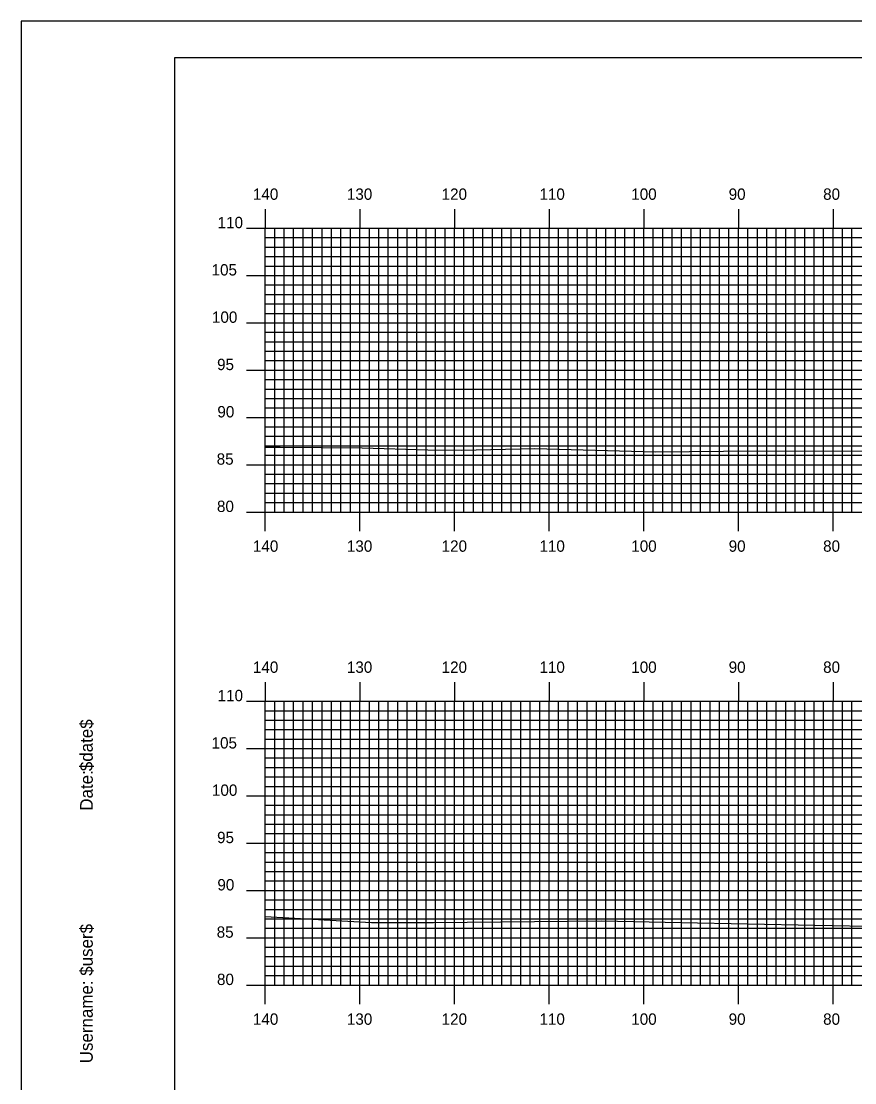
# Model space of a CAD drawing. Extents: x 1762578 to 1762921, y 442591 to 442811.
# Drawn here: x 1762578 to 1762666.1, y 442698.3 to 442810.5 of the extents above; entities that cross this region are included whole.
import ezdxf

# ---------------------------------------------------------------- set-up
doc = ezdxf.new("R2010")
doc.units = 0
for name, color, linetype in [('BORDER', 7, 'Continuous'), ('H_V ANNOTATION', 7, 'Continuous'), ('MAJOR', 7, 'Continuous'), ('MINOR', 7, 'Continuous'), ('PLOT BOUNDARY', 7, 'Continuous'), ('S_Roadway_Centerline', 7, 'Continuous')]:
    doc.layers.add(name, color=color, linetype=linetype)

msp = doc.modelspace()

# ---------------------------------------------------------------- linework, layer by layer
at = {"layer": 'BORDER'}
msp.add_lwpolyline([(1762594.18, 442596.67), (1762914.18, 442596.67), (1762914.18, 442806.67), (1762594.18, 442806.67)], close=True, dxfattribs=at)
at = {"layer": 'MAJOR'}
for p, q in [((1762603.78, 442790.67), (1762603.78, 442788.67)), ((1762613.78, 442790.67), (1762613.78, 442788.67)), ((1762623.78, 442790.67), (1762623.78, 442788.67)), ((1762633.78, 442790.67), (1762633.78, 442788.67)), ((1762643.78, 442790.67), (1762643.78, 442788.67)), ((1762653.78, 442790.67), (1762653.78, 442788.67)), ((1762663.78, 442790.67), (1762663.78, 442788.67)), ((1762601.78, 442788.67), (1762603.78, 442788.67)), ((1762603.78, 442788.67), (1762883.78, 442788.67)), ((1762603.78, 442758.67), (1762603.78, 442788.67)), ((1762603.78, 442758.67), (1762603.78, 442788.67)), ((1762603.78, 442788.67), (1762883.78, 442788.67)), ((1762613.78, 442758.67), (1762613.78, 442788.67)), ((1762623.78, 442758.67), (1762623.78, 442788.67)), ((1762633.78, 442758.67), (1762633.78, 442788.67)), ((1762643.78, 442758.67), (1762643.78, 442788.67)), ((1762653.78, 442758.67), (1762653.78, 442788.67)), ((1762663.78, 442758.67), (1762663.78, 442788.67)), ((1762601.78, 442783.67), (1762603.78, 442783.67)), ((1762603.78, 442783.67), (1762883.78, 442783.67)), ((1762601.78, 442778.67), (1762603.78, 442778.67)), ((1762603.78, 442778.67), (1762883.78, 442778.67)), ((1762601.78, 442773.67), (1762603.78, 442773.67)), ((1762603.78, 442773.67), (1762883.78, 442773.67)), ((1762601.78, 442768.67), (1762603.78, 442768.67)), ((1762603.78, 442768.67), (1762883.78, 442768.67)), ((1762601.78, 442763.67), (1762603.78, 442763.67)), ((1762603.78, 442763.67), (1762883.78, 442763.67)), ((1762601.78, 442758.67), (1762603.78, 442758.67)), ((1762603.78, 442758.67), (1762883.78, 442758.67)), ((1762603.78, 442758.67), (1762883.78, 442758.67)), ((1762603.78, 442756.66), (1762603.78, 442758.67)), ((1762613.78, 442756.66), (1762613.78, 442758.67)), ((1762623.78, 442756.66), (1762623.78, 442758.67)), ((1762633.78, 442756.66), (1762633.78, 442758.67)), ((1762643.78, 442756.66), (1762643.78, 442758.67)), ((1762653.78, 442756.66), (1762653.78, 442758.67)), ((1762663.78, 442756.66), (1762663.78, 442758.67)), ((1762603.78, 442740.67), (1762603.78, 442738.67)), ((1762613.78, 442740.67), (1762613.78, 442738.67)), ((1762623.78, 442740.67), (1762623.78, 442738.67)), ((1762633.78, 442740.67), (1762633.78, 442738.67)), ((1762643.78, 442740.67), (1762643.78, 442738.67)), ((1762653.78, 442740.67), (1762653.78, 442738.67)), ((1762663.78, 442740.67), (1762663.78, 442738.67)), ((1762601.78, 442738.67), (1762603.78, 442738.67)), ((1762603.78, 442738.67), (1762883.78, 442738.67)), ((1762603.78, 442708.67), (1762603.78, 442738.67)), ((1762603.78, 442708.67), (1762603.78, 442738.67)), ((1762603.78, 442738.67), (1762883.78, 442738.67)), ((1762613.78, 442708.67), (1762613.78, 442738.67)), ((1762623.78, 442708.67), (1762623.78, 442738.67)), ((1762633.78, 442708.67), (1762633.78, 442738.67)), ((1762643.78, 442708.67), (1762643.78, 442738.67)), ((1762653.78, 442708.67), (1762653.78, 442738.67)), ((1762663.78, 442708.67), (1762663.78, 442738.67)), ((1762601.78, 442733.67), (1762603.78, 442733.67)), ((1762603.78, 442733.67), (1762883.78, 442733.67)), ((1762601.78, 442728.67), (1762603.78, 442728.67)), ((1762603.78, 442728.67), (1762883.78, 442728.67)), ((1762601.78, 442723.67), (1762603.78, 442723.67)), ((1762603.78, 442723.67), (1762883.78, 442723.67)), ((1762601.78, 442718.67), (1762603.78, 442718.67)), ((1762603.78, 442718.67), (1762883.78, 442718.67)), ((1762601.78, 442713.67), (1762603.78, 442713.67)), ((1762603.78, 442713.67), (1762883.78, 442713.67)), ((1762601.78, 442708.67), (1762603.78, 442708.67)), ((1762603.78, 442708.67), (1762883.78, 442708.67)), ((1762603.78, 442708.67), (1762883.78, 442708.67)), ((1762603.78, 442706.66), (1762603.78, 442708.67)), ((1762613.78, 442706.66), (1762613.78, 442708.67)), ((1762623.78, 442706.66), (1762623.78, 442708.67)), ((1762633.78, 442706.66), (1762633.78, 442708.67)), ((1762643.78, 442706.66), (1762643.78, 442708.67)), ((1762653.78, 442706.66), (1762653.78, 442708.67)), ((1762663.78, 442706.66), (1762663.78, 442708.67))]:
    msp.add_line(p, q, dxfattribs=at)
at = {"layer": 'MINOR'}
for p, q in [((1762604.78, 442758.67), (1762604.78, 442788.67)), ((1762605.78, 442758.67), (1762605.78, 442788.67)), ((1762606.78, 442758.67), (1762606.78, 442788.67)), ((1762607.78, 442758.67), (1762607.78, 442788.67)), ((1762608.78, 442758.67), (1762608.78, 442788.67)), ((1762609.78, 442758.67), (1762609.78, 442788.67)), ((1762610.78, 442758.67), (1762610.78, 442788.67)), ((1762611.78, 442758.67), (1762611.78, 442788.67)), ((1762612.78, 442758.67), (1762612.78, 442788.67)), ((1762614.78, 442758.67), (1762614.78, 442788.67)), ((1762615.78, 442758.67), (1762615.78, 442788.67)), ((1762616.78, 442758.67), (1762616.78, 442788.67)), ((1762617.78, 442758.67), (1762617.78, 442788.67)), ((1762618.78, 442758.67), (1762618.78, 442788.67)), ((1762619.78, 442758.67), (1762619.78, 442788.67)), ((1762620.78, 442758.67), (1762620.78, 442788.67)), ((1762621.78, 442758.67), (1762621.78, 442788.67)), ((1762622.78, 442758.67), (1762622.78, 442788.67)), ((1762624.78, 442758.67), (1762624.78, 442788.67)), ((1762625.78, 442758.67), (1762625.78, 442788.67)), ((1762626.78, 442758.67), (1762626.78, 442788.67)), ((1762627.78, 442758.67), (1762627.78, 442788.67)), ((1762628.78, 442758.67), (1762628.78, 442788.67)), ((1762629.78, 442758.67), (1762629.78, 442788.67)), ((1762630.78, 442758.67), (1762630.78, 442788.67)), ((1762631.78, 442758.67), (1762631.78, 442788.67)), ((1762632.78, 442758.67), (1762632.78, 442788.67)), ((1762634.78, 442758.67), (1762634.78, 442788.67)), ((1762635.78, 442758.67), (1762635.78, 442788.67)), ((1762636.78, 442758.67), (1762636.78, 442788.67)), ((1762637.78, 442758.67), (1762637.78, 442788.67)), ((1762638.78, 442758.67), (1762638.78, 442788.67)), ((1762639.78, 442758.67), (1762639.78, 442788.67)), ((1762640.78, 442758.67), (1762640.78, 442788.67)), ((1762641.78, 442758.67), (1762641.78, 442788.67)), ((1762642.78, 442758.67), (1762642.78, 442788.67)), ((1762644.78, 442758.67), (1762644.78, 442788.67)), ((1762645.78, 442758.67), (1762645.78, 442788.67)), ((1762646.78, 442758.67), (1762646.78, 442788.67)), ((1762647.78, 442758.67), (1762647.78, 442788.67)), ((1762648.78, 442758.67), (1762648.78, 442788.67)), ((1762649.78, 442758.67), (1762649.78, 442788.67)), ((1762650.78, 442758.67), (1762650.78, 442788.67)), ((1762651.78, 442758.67), (1762651.78, 442788.67)), ((1762652.78, 442758.67), (1762652.78, 442788.67)), ((1762654.78, 442758.67), (1762654.78, 442788.67)), ((1762655.78, 442758.67), (1762655.78, 442788.67)), ((1762656.78, 442758.67), (1762656.78, 442788.67)), ((1762657.78, 442758.67), (1762657.78, 442788.67)), ((1762658.78, 442758.67), (1762658.78, 442788.67)), ((1762659.78, 442758.67), (1762659.78, 442788.67)), ((1762660.78, 442758.67), (1762660.78, 442788.67)), ((1762661.78, 442758.67), (1762661.78, 442788.67)), ((1762662.78, 442758.67), (1762662.78, 442788.67)), ((1762664.78, 442758.67), (1762664.78, 442788.67)), ((1762665.78, 442758.67), (1762665.78, 442788.67)), ((1762603.78, 442787.67), (1762883.78, 442787.67)), ((1762603.78, 442787.67), (1762605.78, 442787.67)), ((1762603.78, 442786.67), (1762883.78, 442786.67)), ((1762603.78, 442786.67), (1762605.78, 442786.67)), ((1762603.78, 442785.67), (1762883.78, 442785.67)), ((1762603.78, 442785.67), (1762605.78, 442785.67)), ((1762603.78, 442784.67), (1762883.78, 442784.67)), ((1762603.78, 442784.67), (1762605.78, 442784.67)), ((1762603.78, 442782.67), (1762883.78, 442782.67)), ((1762603.78, 442782.67), (1762605.78, 442782.67)), ((1762603.78, 442781.67), (1762883.78, 442781.67)), ((1762603.78, 442781.67), (1762605.78, 442781.67)), ((1762603.78, 442780.67), (1762883.78, 442780.67)), ((1762603.78, 442780.67), (1762605.78, 442780.67)), ((1762603.78, 442779.67), (1762883.78, 442779.67)), ((1762603.78, 442779.67), (1762605.78, 442779.67)), ((1762603.78, 442777.67), (1762883.78, 442777.67)), ((1762603.78, 442777.67), (1762605.78, 442777.67)), ((1762603.78, 442776.67), (1762883.78, 442776.67)), ((1762603.78, 442776.67), (1762605.78, 442776.67)), ((1762603.78, 442775.67), (1762883.78, 442775.67)), ((1762603.78, 442775.67), (1762605.78, 442775.67)), ((1762603.78, 442774.67), (1762883.78, 442774.67)), ((1762603.78, 442774.67), (1762605.78, 442774.67)), ((1762603.78, 442772.67), (1762883.78, 442772.67)), ((1762603.78, 442772.67), (1762605.78, 442772.67)), ((1762603.78, 442771.67), (1762883.78, 442771.67)), ((1762603.78, 442771.67), (1762605.78, 442771.67)), ((1762603.78, 442770.67), (1762883.78, 442770.67)), ((1762603.78, 442770.67), (1762605.78, 442770.67)), ((1762603.78, 442769.67), (1762883.78, 442769.67)), ((1762603.78, 442769.67), (1762605.78, 442769.67)), ((1762603.78, 442767.67), (1762883.78, 442767.67)), ((1762603.78, 442767.67), (1762605.78, 442767.67)), ((1762603.78, 442766.67), (1762883.78, 442766.67)), ((1762603.78, 442766.67), (1762605.78, 442766.67)), ((1762603.78, 442765.67), (1762883.78, 442765.67)), ((1762603.78, 442765.67), (1762605.78, 442765.67)), ((1762603.78, 442764.67), (1762883.78, 442764.67)), ((1762603.78, 442764.67), (1762605.78, 442764.67)), ((1762603.78, 442762.67), (1762883.78, 442762.67)), ((1762603.78, 442762.67), (1762605.78, 442762.67)), ((1762603.78, 442761.67), (1762883.78, 442761.67)), ((1762603.78, 442761.67), (1762605.78, 442761.67)), ((1762603.78, 442760.67), (1762883.78, 442760.67)), ((1762603.78, 442760.67), (1762605.78, 442760.67)), ((1762603.78, 442759.67), (1762883.78, 442759.67)), ((1762603.78, 442759.67), (1762605.78, 442759.67)), ((1762604.78, 442708.67), (1762604.78, 442738.67)), ((1762605.78, 442708.67), (1762605.78, 442738.67)), ((1762606.78, 442708.67), (1762606.78, 442738.67)), ((1762607.78, 442708.67), (1762607.78, 442738.67)), ((1762608.78, 442708.67), (1762608.78, 442738.67)), ((1762609.78, 442708.67), (1762609.78, 442738.67)), ((1762610.78, 442708.67), (1762610.78, 442738.67)), ((1762611.78, 442708.67), (1762611.78, 442738.67)), ((1762612.78, 442708.67), (1762612.78, 442738.67)), ((1762614.78, 442708.67), (1762614.78, 442738.67)), ((1762615.78, 442708.67), (1762615.78, 442738.67)), ((1762616.78, 442708.67), (1762616.78, 442738.67)), ((1762617.78, 442708.67), (1762617.78, 442738.67)), ((1762618.78, 442708.67), (1762618.78, 442738.67)), ((1762619.78, 442708.67), (1762619.78, 442738.67)), ((1762620.78, 442708.67), (1762620.78, 442738.67)), ((1762621.78, 442708.67), (1762621.78, 442738.67)), ((1762622.78, 442708.67), (1762622.78, 442738.67)), ((1762624.78, 442708.67), (1762624.78, 442738.67)), ((1762625.78, 442708.67), (1762625.78, 442738.67)), ((1762626.78, 442708.67), (1762626.78, 442738.67)), ((1762627.78, 442708.67), (1762627.78, 442738.67)), ((1762628.78, 442708.67), (1762628.78, 442738.67)), ((1762629.78, 442708.67), (1762629.78, 442738.67)), ((1762630.78, 442708.67), (1762630.78, 442738.67)), ((1762631.78, 442708.67), (1762631.78, 442738.67)), ((1762632.78, 442708.67), (1762632.78, 442738.67)), ((1762634.78, 442708.67), (1762634.78, 442738.67)), ((1762635.78, 442708.67), (1762635.78, 442738.67)), ((1762636.78, 442708.67), (1762636.78, 442738.67)), ((1762637.78, 442708.67), (1762637.78, 442738.67)), ((1762638.78, 442708.67), (1762638.78, 442738.67)), ((1762639.78, 442708.67), (1762639.78, 442738.67)), ((1762640.78, 442708.67), (1762640.78, 442738.67)), ((1762641.78, 442708.67), (1762641.78, 442738.67)), ((1762642.78, 442708.67), (1762642.78, 442738.67)), ((1762644.78, 442708.67), (1762644.78, 442738.67)), ((1762645.78, 442708.67), (1762645.78, 442738.67)), ((1762646.78, 442708.67), (1762646.78, 442738.67)), ((1762647.78, 442708.67), (1762647.78, 442738.67)), ((1762648.78, 442708.67), (1762648.78, 442738.67)), ((1762649.78, 442708.67), (1762649.78, 442738.67)), ((1762650.78, 442708.67), (1762650.78, 442738.67)), ((1762651.78, 442708.67), (1762651.78, 442738.67)), ((1762652.78, 442708.67), (1762652.78, 442738.67)), ((1762654.78, 442708.67), (1762654.78, 442738.67)), ((1762655.78, 442708.67), (1762655.78, 442738.67)), ((1762656.78, 442708.67), (1762656.78, 442738.67)), ((1762657.78, 442708.67), (1762657.78, 442738.67)), ((1762658.78, 442708.67), (1762658.78, 442738.67)), ((1762659.78, 442708.67), (1762659.78, 442738.67)), ((1762660.78, 442708.67), (1762660.78, 442738.67)), ((1762661.78, 442708.67), (1762661.78, 442738.67)), ((1762662.78, 442708.67), (1762662.78, 442738.67)), ((1762664.78, 442708.67), (1762664.78, 442738.67)), ((1762665.78, 442708.67), (1762665.78, 442738.67)), ((1762603.78, 442737.67), (1762883.78, 442737.67)), ((1762603.78, 442737.67), (1762605.78, 442737.67)), ((1762603.78, 442736.67), (1762883.78, 442736.67)), ((1762603.78, 442736.67), (1762605.78, 442736.67)), ((1762603.78, 442735.67), (1762883.78, 442735.67)), ((1762603.78, 442735.67), (1762605.78, 442735.67)), ((1762603.78, 442734.67), (1762883.78, 442734.67)), ((1762603.78, 442734.67), (1762605.78, 442734.67)), ((1762603.78, 442732.67), (1762883.78, 442732.67)), ((1762603.78, 442732.67), (1762605.78, 442732.67)), ((1762603.78, 442731.67), (1762883.78, 442731.67)), ((1762603.78, 442731.67), (1762605.78, 442731.67)), ((1762603.78, 442730.67), (1762883.78, 442730.67)), ((1762603.78, 442730.67), (1762605.78, 442730.67)), ((1762603.78, 442729.67), (1762883.78, 442729.67)), ((1762603.78, 442729.67), (1762605.78, 442729.67)), ((1762603.78, 442727.67), (1762883.78, 442727.67)), ((1762603.78, 442727.67), (1762605.78, 442727.67)), ((1762603.78, 442726.67), (1762883.78, 442726.67)), ((1762603.78, 442726.67), (1762605.78, 442726.67)), ((1762603.78, 442725.67), (1762883.78, 442725.67)), ((1762603.78, 442725.67), (1762605.78, 442725.67)), ((1762603.78, 442724.67), (1762883.78, 442724.67)), ((1762603.78, 442724.67), (1762605.78, 442724.67)), ((1762603.78, 442722.67), (1762883.78, 442722.67)), ((1762603.78, 442722.67), (1762605.78, 442722.67)), ((1762603.78, 442721.67), (1762883.78, 442721.67)), ((1762603.78, 442721.67), (1762605.78, 442721.67)), ((1762603.78, 442720.67), (1762883.78, 442720.67)), ((1762603.78, 442720.67), (1762605.78, 442720.67)), ((1762603.78, 442719.67), (1762883.78, 442719.67)), ((1762603.78, 442719.67), (1762605.78, 442719.67)), ((1762603.78, 442717.67), (1762883.78, 442717.67)), ((1762603.78, 442717.67), (1762605.78, 442717.67)), ((1762603.78, 442716.67), (1762883.78, 442716.67)), ((1762603.78, 442716.67), (1762605.78, 442716.67)), ((1762603.78, 442715.67), (1762883.78, 442715.67)), ((1762603.78, 442715.67), (1762605.78, 442715.67)), ((1762603.78, 442714.67), (1762883.78, 442714.67)), ((1762603.78, 442714.67), (1762605.78, 442714.67)), ((1762603.78, 442712.67), (1762883.78, 442712.67)), ((1762603.78, 442712.67), (1762605.78, 442712.67)), ((1762603.78, 442711.67), (1762883.78, 442711.67)), ((1762603.78, 442711.67), (1762605.78, 442711.67)), ((1762603.78, 442710.67), (1762883.78, 442710.67)), ((1762603.78, 442710.67), (1762605.78, 442710.67)), ((1762603.78, 442709.67), (1762883.78, 442709.67)), ((1762603.78, 442709.67), (1762605.78, 442709.67))]:
    msp.add_line(p, q, dxfattribs=at)
at = {"layer": 'PLOT BOUNDARY'}
msp.add_lwpolyline([(1762577.99, 442590.55), (1762917.99, 442590.55), (1762917.99, 442810.55), (1762577.99, 442810.55)], close=True, dxfattribs=at)
at = {"layer": 'S_Roadway_Centerline'}
for points in [[(1762603.78, 442765.51), (1762605.34, 442765.52), (1762614.03, 442765.44), (1762620.96, 442765.24), (1762624.53, 442765.22), (1762632.27, 442765.37), (1762645.06, 442765.04), (1762655.76, 442765.13), (1762679.13, 442765.06)], [(1762603.78, 442715.93), (1762615, 442715.29), (1762621.56, 442715.29), (1762639.34, 442715.45), (1762647.68, 442715.27), (1762661.87, 442715), (1762669.22, 442714.86), (1762671.41, 442714.79), (1762686.85, 442714.31), (1762690.37, 442714.22), (1762692.53, 442714.2), (1762703.22, 442714.51), (1762726.59, 442715.11), (1762729.34, 442715.14), (1762733.92, 442715.11), (1762750.45, 442715.09), (1762756.11, 442715.29), (1762766.02, 442715.74), (1762774.05, 442716.61), (1762784.72, 442717.56), (1762788.78, 442717.85), (1762798.29, 442718.48), (1762804.53, 442719), (1762810.77, 442719.38)]]:
    msp.add_lwpolyline(points, dxfattribs=at)

# ---------------------------------------------------------------- texts
at = {"layer": 'BORDER'}
for s, p in [('$date$', (1762585.55, 442731.28)), ('Date:', (1762585.55, 442727.1)), ('$user$', (1762585.55, 442709.65)), ('Username:', (1762585.55, 442700.4))]:
    msp.add_text(s, height=1.339, rotation=90, dxfattribs=at).set_placement(p)
at = {"layer": 'H_V ANNOTATION'}
for s, p in [('140', (1762602.48, 442791.67)), ('130', (1762612.41, 442791.67)), ('120', (1762622.42, 442791.67)), ('110', (1762632.76, 442791.67)), ('100', (1762642.46, 442791.67)), ('90', (1762652.75, 442791.67)), ('80', (1762662.73, 442791.67)), ('110', (1762598.75, 442788.67)), ('105', (1762598.11, 442783.67)), ('100', (1762598.15, 442778.67)), ('95', (1762598.69, 442773.67)), ('90', (1762598.72, 442768.67)), ('85', (1762598.65, 442763.67)), ('80', (1762598.68, 442758.67)), ('140', (1762602.48, 442754.47)), ('130', (1762612.41, 442754.47)), ('120', (1762622.42, 442754.47)), ('110', (1762632.76, 442754.47)), ('100', (1762642.46, 442754.47)), ('90', (1762652.75, 442754.47)), ('80', (1762662.73, 442754.47)), ('140', (1762602.48, 442741.67)), ('130', (1762612.41, 442741.67)), ('120', (1762622.42, 442741.67)), ('110', (1762632.76, 442741.67)), ('100', (1762642.46, 442741.67)), ('90', (1762652.75, 442741.67)), ('80', (1762662.73, 442741.67)), ('110', (1762598.75, 442738.67)), ('105', (1762598.11, 442733.67)), ('100', (1762598.15, 442728.67)), ('95', (1762598.69, 442723.67)), ('90', (1762598.72, 442718.67)), ('85', (1762598.65, 442713.67)), ('80', (1762598.68, 442708.67)), ('140', (1762602.48, 442704.47)), ('130', (1762612.41, 442704.47)), ('120', (1762622.42, 442704.47)), ('110', (1762632.76, 442704.47)), ('100', (1762642.46, 442704.47)), ('90', (1762652.75, 442704.47)), ('80', (1762662.73, 442704.47))]:
    msp.add_text(s, height=1.2, dxfattribs=at).set_placement(p)
at = {"layer": 'MAJOR'}
for p in [(1762603.77, 442758.67), (1762603.77, 442708.67)]:
    msp.add_text('-', height=0.012, dxfattribs=at).set_placement(p)

doc.saveas('drawing.dxf')
